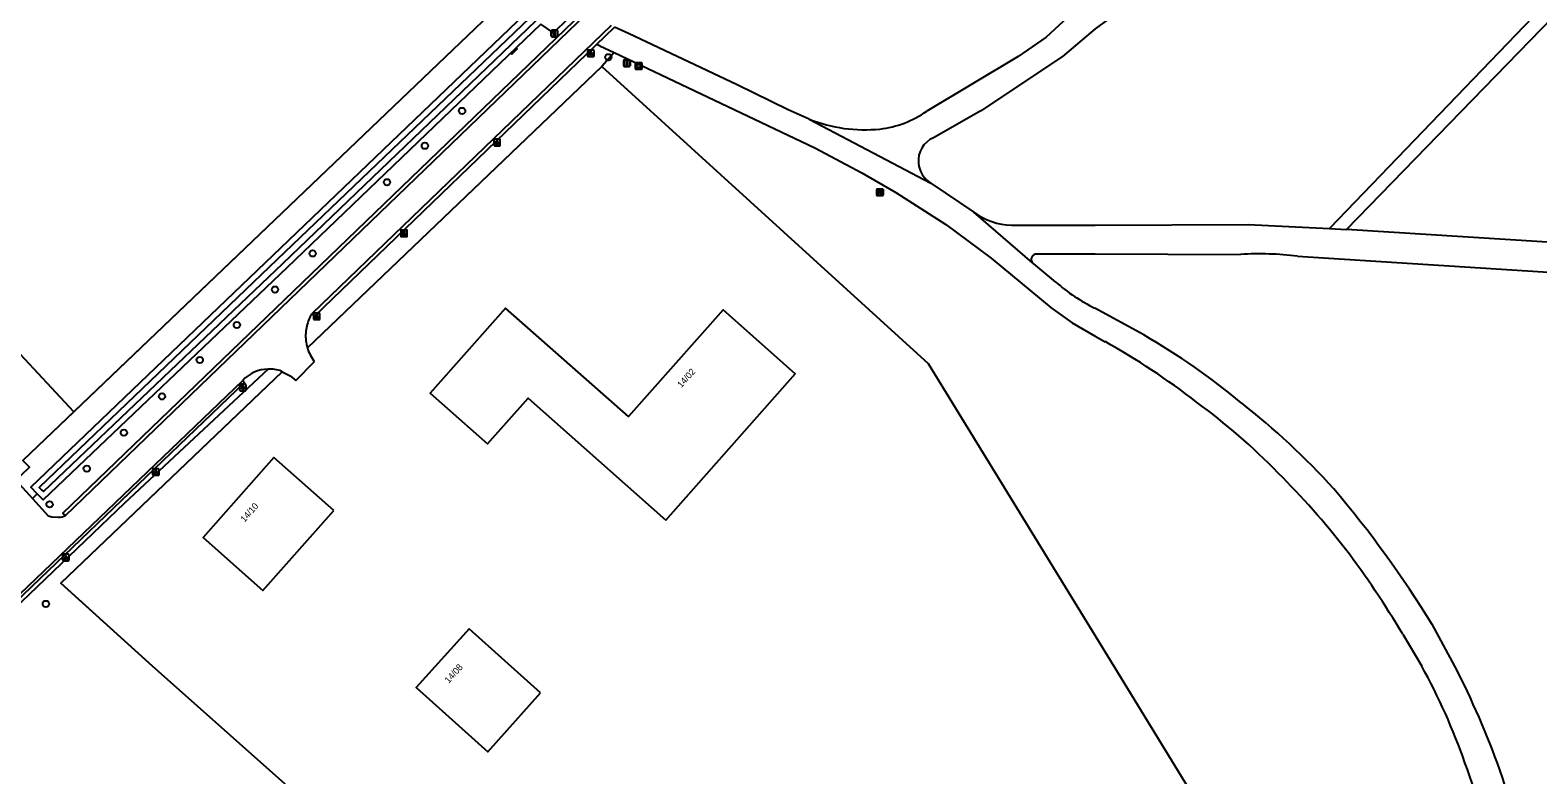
# Model space of a CAD drawing. Extents: x 157154 to 159278, y 385000 to 386650.
# Drawn here: x 157835.7 to 158068.3, y 385983.3 to 386098.1 of the extents above; entities that cross this region are included whole.
import ezdxf

# ---------------------------------------------------------------- set-up
doc = ezdxf.new("R2010")
doc.units = 0
for name, color, linetype in [('IMGEO_Afsluitpaal', 7, 'Continuous'), ('IMGEO_Afvalbak', 7, 'Continuous'), ('IMGEO_Bank', 7, 'Continuous'), ('IMGEO_Boom', 7, 'Continuous'), ('IMGEO_Bouwland', 7, 'Continuous'), ('IMGEO_Gemengd_bos', 7, 'Continuous'), ('IMGEO_Groenvoorziening', 7, 'Continuous'), ('IMGEO_Hek', 7, 'Continuous'), ('IMGEO_Lichtpunt', 7, 'Continuous'), ('IMGEO_Muur', 7, 'Continuous'), ('IMGEO_Pand', 7, 'Continuous'), ('IMGEO_Pand_nummerreeks', 7, 'Continuous'), ('IMGEO_Rijbaan_lokaal_halfverhard', 7, 'Continuous'), ('IMGEO_Rijbaan_lokaal_open', 7, 'Continuous'), ('IMGEO_Verkeersbordpaal', 7, 'Continuous'), ('IMGEO_Voetpad_halfverhard', 7, 'Continuous'), ('IMGEO_Waterloop', 7, 'Continuous')]:
    doc.layers.add(name, color=color, linetype=linetype)

msp = doc.modelspace()

# ---------------------------------------------------------------- linework, layer by layer
at = {"layer": 'IMGEO_Afsluitpaal'}
for p, q in [((157916.1, 386097.15), (157916.1, 386097.95)), ((157916.1, 386097.95), (157916.1, 386097.15)), ((157916.2, 386098.05), (157916.99, 386098.05)), ((157916.99, 386098.05), (157916.2, 386098.05)), ((157916.99, 386097.05), (157916.2, 386097.05)), ((157916.2, 386097.05), (157916.99, 386097.05)), ((157917.09, 386097.95), (157917.09, 386097.15)), ((157917.09, 386097.15), (157917.09, 386097.95))]:
    msp.add_line(p, q, dxfattribs=at)
msp.add_lwpolyline([(157916.52, 386097.93), (157916.67, 386097.93), (157916.67, 386097.18), (157916.52, 386097.18), (157916.52, 386097.93)], dxfattribs=at)
for centre, start, end in [((157916.2, 386097.95), 90, 180), ((157916.2, 386097.95), 90, 180), ((157916.2, 386097.15), 180, 270), ((157916.2, 386097.15), 180, 270), ((157916.99, 386097.95), 0, 90), ((157916.99, 386097.95), 360, 90), ((157916.99, 386097.15), 270, 0), ((157916.99, 386097.15), 270, 0)]:
    msp.add_arc(centre, 0.1, start, end, dxfattribs=at)
at = {"layer": 'IMGEO_Afvalbak'}
for p, q in [((157929.09, 386092.15), (157929.09, 386092.95)), ((157929.09, 386092.95), (157929.09, 386092.15)), ((157929.19, 386093.05), (157929.98, 386093.05)), ((157929.98, 386093.05), (157929.19, 386093.05)), ((157930.08, 386092.95), (157930.08, 386092.15)), ((157930.08, 386092.15), (157930.08, 386092.95)), ((157929.98, 386092.05), (157929.19, 386092.05)), ((157929.19, 386092.05), (157929.98, 386092.05))]:
    msp.add_line(p, q, dxfattribs=at)
msp.add_lwpolyline([(157929.23, 386092.77), (157929.94, 386092.77), (157929.79, 386092.3), (157929.38, 386092.3), (157929.23, 386092.77)], dxfattribs=at)
for centre, start, end in [((157929.19, 386092.95), 90, 180), ((157929.19, 386092.95), 90, 180), ((157929.98, 386092.95), 0, 90), ((157929.98, 386092.95), 360, 90), ((157929.19, 386092.15), 180, 270), ((157929.19, 386092.15), 180, 270), ((157929.98, 386092.15), 270, 0), ((157929.98, 386092.15), 270, 0)]:
    msp.add_arc(centre, 0.1, start, end, dxfattribs=at)
at = {"layer": 'IMGEO_Bank'}
for p, q in [((157966.3, 386072.65), (157966.3, 386073.49)), ((157966.3, 386073.49), (157966.3, 386072.65)), ((157966.37, 386073.57), (157967.22, 386073.57)), ((157967.22, 386073.57), (157966.37, 386073.57)), ((157967.23, 386072.57), (157966.38, 386072.57)), ((157966.38, 386072.57), (157967.23, 386072.57)), ((157967, 386072.97), (157966.6, 386072.97)), ((157966.61, 386073.08), (157966.61, 386073.18)), ((157966.65, 386073.18), (157966.65, 386073.08)), ((157966.94, 386073.19), (157966.66, 386073.19)), ((157966.66, 386073.07), (157966.94, 386073.07)), ((157966.95, 386073.08), (157966.95, 386073.18)), ((157966.99, 386073.18), (157966.99, 386073.08)), ((157967.3, 386073.5), (157967.3, 386072.66)), ((157967.3, 386072.66), (157967.3, 386073.5))]:
    msp.add_line(p, q, dxfattribs=at)
for points in [[(157966.55, 386072.97), (157966.4, 386072.97), (157966.52, 386073.07), (157966.6, 386073.07)], [(157966.6, 386073.19), (157966.52, 386073.19), (157966.52, 386073.35), (157967.08, 386073.35), (157967.08, 386073.19), (157967, 386073.19)], [(157966.6, 386072.96), (157966.6, 386072.75), (157966.55, 386072.75), (157966.55, 386072.96)], [(157967, 386073.07), (157967.08, 386073.07), (157967.19, 386072.97), (157967.05, 386072.97)], [(157967.05, 386072.96), (157967.05, 386072.75), (157967, 386072.75), (157967, 386072.96)]]:
    msp.add_lwpolyline(points, dxfattribs=at)
for centre, radius, start, end in [((157966.38, 386073.49), 0.0779, 92.4484, 184.2845), ((157966.38, 386073.49), 0.0779, 92.4484, 184.2845), ((157966.38, 386072.65), 0.0779, 182.4484, 274.2845), ((157966.38, 386072.65), 0.0779, 182.4484, 274.2845), ((157966.55, 386072.96), 0.00671, 2.8957, 87.1043), ((157966.6, 386073.18), 0.00671, 2.8957, 87.1043), ((157966.6, 386073.08), 0.00671, 272.8957, 357.1043), ((157966.6, 386072.96), 0.00671, 92.8957, 177.1043), ((157966.66, 386073.18), 0.00671, 92.8957, 177.1043), ((157966.66, 386073.08), 0.00671, 182.8957, 267.1043), ((157966.94, 386073.18), 0.00671, 2.8957, 87.1043), ((157966.94, 386073.08), 0.00671, 272.8957, 357.1043), ((157967, 386073.18), 0.00671, 92.8957, 177.1043), ((157967, 386073.08), 0.00671, 182.8957, 267.1043), ((157967, 386072.96), 0.00671, 2.8957, 87.1043), ((157967.05, 386072.96), 0.00671, 92.8957, 177.1043), ((157967.22, 386073.49), 0.0779, 2.4484, 94.2845), ((157967.22, 386073.49), 0.0779, 2.4484, 94.2845), ((157967.22, 386072.65), 0.0779, 272.4484, 4.2845), ((157967.22, 386072.65), 0.0779, 272.4484, 4.2845)]:
    msp.add_arc(centre, radius, start, end, dxfattribs=at)
at = {"layer": 'IMGEO_Boom'}
for centre in [(157924.92, 386093.9), (157902.35, 386085.62), (157896.61, 386080.24), (157890.78, 386074.63), (157879.3, 386063.64), (157873.49, 386058.08), (157867.61, 386052.62), (157861.89, 386047.22), (157856.07, 386041.6), (157850.18, 386036.01), (157844.46, 386030.47), (157838.72, 386024.96), (157838.15, 386009.61)]:
    msp.add_circle(centre, 0.489, dxfattribs=at)
at = {"layer": 'IMGEO_Bouwland'}
for points in [[(157842.48, 386039.2), (157804.71, 386079.73), (157824.5, 386097.81), (157874.85, 386146.92), (157921.22, 386191.28), (157933.34, 386204.01)], [(157907.89, 386100.62), (157906.64, 386100.46), (157842.48, 386039.2)]]:
    msp.add_lwpolyline(points, dxfattribs=at)
at = {"layer": 'IMGEO_Gemengd_bos'}
for points in [[(157925.82, 386094.62), (157923.9, 386092.49)], [(157923.9, 386092.49), (157974.24, 386046.68), (158002.86, 386000), (158038.99, 385941.05), (158062.63, 385902.16)]]:
    msp.add_lwpolyline(points, dxfattribs=at)
at = {"layer": 'IMGEO_Groenvoorziening'}
for points in [[(157836.83, 386026.59), (157835.85, 386027.6), (157873.22, 386063.38), (157912.1, 386100.6)], [(157914.49, 386098.99), (157875.32, 386061.42), (157837.74, 386025.65), (157836.83, 386026.59)], [(157878.48, 386049.1), (157923.9, 386092.49)], [(157872.43, 386045.82), (157850.3, 386025.12), (157807.42, 385984.13), (157804.36, 385981.2)], [(157921.45, 385940.96), (157882.35, 385975.36), (157854.58, 386000), (157840.47, 386012.79), (157874.62, 386045.41)], [(157842.48, 386039.2), (157834.62, 386031.7), (157835.6, 386030.67), (157834.29, 386029.42), (157833.54, 386028.71)], [(157836.83, 386026.59), (157836.07, 386025.87)]]:
    msp.add_lwpolyline(points, dxfattribs=at)
at = {"layer": 'IMGEO_Hek'}
for points in [[(157906.64, 386100.46), (157834.62, 386031.7)], [(157923.9, 386092.49), (157878.48, 386049.1)], [(157874.62, 386045.41), (157840.47, 386012.79)], [(157840.47, 386012.79), (157854.58, 386000), (157882.35, 385975.36), (157921.45, 385940.96)]]:
    msp.add_lwpolyline(points, dxfattribs=at)
at = {"layer": 'IMGEO_Lichtpunt'}
for p, q in [((157921.71, 386094.91), (157921.71, 386094.1)), ((157921.71, 386094.91), (157921.71, 386094.1)), ((157922.61, 386095.01), (157921.81, 386095.01)), ((157922.61, 386095.01), (157921.81, 386095.01)), ((157922.71, 386094.1), (157922.71, 386094.91)), ((157922.71, 386094.1), (157922.71, 386094.91)), ((157921.81, 386094.01), (157922.61, 386094.01)), ((157921.81, 386094.01), (157922.61, 386094.01)), ((157907.25, 386081.14), (157907.25, 386080.33)), ((157907.25, 386081.14), (157907.25, 386080.33)), ((157908.15, 386081.24), (157907.34, 386081.24)), ((157908.15, 386081.24), (157907.34, 386081.24)), ((157908.24, 386080.33), (157908.24, 386081.14)), ((157908.24, 386080.33), (157908.24, 386081.14)), ((157907.34, 386080.24), (157908.15, 386080.24)), ((157907.34, 386080.24), (157908.15, 386080.24)), ((157892.9, 386067.14), (157892.9, 386066.33)), ((157892.9, 386067.14), (157892.9, 386066.33)), ((157893.8, 386067.23), (157892.99, 386067.23)), ((157893.8, 386067.23), (157892.99, 386067.23)), ((157893.9, 386066.33), (157893.9, 386067.14)), ((157893.9, 386066.33), (157893.9, 386067.14)), ((157892.99, 386066.24), (157893.8, 386066.24)), ((157892.99, 386066.24), (157893.8, 386066.24)), ((157879.43, 386054.34), (157879.43, 386053.53)), ((157879.43, 386054.34), (157879.43, 386053.53)), ((157880.34, 386054.43), (157879.53, 386054.43)), ((157880.34, 386054.43), (157879.53, 386054.43)), ((157879.53, 386053.44), (157880.34, 386053.44)), ((157879.53, 386053.44), (157880.34, 386053.44)), ((157880.43, 386053.53), (157880.43, 386054.34)), ((157880.43, 386053.53), (157880.43, 386054.34)), ((157868.94, 386043.48), (157868.13, 386043.48)), ((157868.94, 386043.48), (157868.13, 386043.48)), ((157868.04, 386043.38), (157868.04, 386042.57)), ((157868.04, 386043.38), (157868.04, 386042.57)), ((157868.13, 386042.48), (157868.94, 386042.48)), ((157868.13, 386042.48), (157868.94, 386042.48)), ((157869.04, 386042.57), (157869.04, 386043.38)), ((157869.04, 386042.57), (157869.04, 386043.38)), ((157854.61, 386030.34), (157854.61, 386029.54)), ((157854.61, 386030.34), (157854.61, 386029.54)), ((157855.51, 386030.44), (157854.7, 386030.44)), ((157855.51, 386030.44), (157854.7, 386030.44)), ((157855.6, 386029.54), (157855.6, 386030.34)), ((157855.6, 386029.54), (157855.6, 386030.34)), ((157854.7, 386029.44), (157855.51, 386029.44)), ((157854.7, 386029.44), (157855.51, 386029.44)), ((157840.73, 386017.16), (157840.73, 386016.35)), ((157840.73, 386017.16), (157840.73, 386016.35)), ((157841.63, 386017.26), (157840.82, 386017.26)), ((157841.63, 386017.26), (157840.82, 386017.26)), ((157840.82, 386016.26), (157841.63, 386016.26)), ((157840.82, 386016.26), (157841.63, 386016.26)), ((157841.72, 386016.35), (157841.72, 386017.16)), ((157841.72, 386016.35), (157841.72, 386017.16))]:
    msp.add_line(p, q, dxfattribs=at)
for points in [[(157922.09, 386094.57), (157922.12, 386094.55), (157921.94, 386094.28), (157921.9, 386094.31), (157922.09, 386094.57)], [(157922.19, 386094.53), (157922.23, 386094.53), (157922.23, 386094.2), (157922.19, 386094.2), (157922.19, 386094.53)], [(157922.3, 386094.55), (157922.34, 386094.57), (157922.52, 386094.31), (157922.48, 386094.28), (157922.3, 386094.55)], [(157907.62, 386080.8), (157907.66, 386080.78), (157907.47, 386080.51), (157907.43, 386080.54), (157907.62, 386080.8)], [(157907.72, 386080.76), (157907.77, 386080.76), (157907.77, 386080.43), (157907.72, 386080.43), (157907.72, 386080.76)], [(157907.83, 386080.78), (157907.87, 386080.8), (157908.06, 386080.54), (157908.02, 386080.51), (157907.83, 386080.78)], [(157893.27, 386066.8), (157893.31, 386066.77), (157893.13, 386066.51), (157893.09, 386066.54), (157893.27, 386066.8)], [(157893.38, 386066.75), (157893.42, 386066.75), (157893.42, 386066.43), (157893.38, 386066.43), (157893.38, 386066.75)], [(157893.49, 386066.77), (157893.52, 386066.8), (157893.71, 386066.54), (157893.67, 386066.51), (157893.49, 386066.77)], [(157879.81, 386054), (157879.85, 386053.97), (157879.66, 386053.71), (157879.62, 386053.74), (157879.81, 386054)], [(157879.91, 386053.95), (157879.96, 386053.95), (157879.96, 386053.63), (157879.91, 386053.63), (157879.91, 386053.95)], [(157880.02, 386053.97), (157880.06, 386054), (157880.25, 386053.74), (157880.21, 386053.71), (157880.02, 386053.97)], [(157868.41, 386043.04), (157868.45, 386043.02), (157868.27, 386042.75), (157868.23, 386042.78), (157868.41, 386043.04)], [(157868.52, 386043), (157868.56, 386043), (157868.56, 386042.67), (157868.52, 386042.67), (157868.52, 386043)], [(157868.63, 386043.02), (157868.66, 386043.04), (157868.85, 386042.78), (157868.81, 386042.75), (157868.63, 386043.02)], [(157854.98, 386030.01), (157855.02, 386029.98), (157854.83, 386029.72), (157854.79, 386029.74), (157854.98, 386030.01)], [(157855.08, 386029.96), (157855.13, 386029.96), (157855.13, 386029.64), (157855.08, 386029.64), (157855.08, 386029.96)], [(157855.19, 386029.98), (157855.23, 386030.01), (157855.42, 386029.74), (157855.38, 386029.72), (157855.19, 386029.98)], [(157841.1, 386016.82), (157841.14, 386016.8), (157840.95, 386016.53), (157840.91, 386016.56), (157841.1, 386016.82)], [(157841.2, 386016.78), (157841.25, 386016.78), (157841.25, 386016.45), (157841.2, 386016.45), (157841.2, 386016.78)], [(157841.31, 386016.8), (157841.35, 386016.82), (157841.54, 386016.56), (157841.5, 386016.53), (157841.31, 386016.8)]]:
    msp.add_lwpolyline(points, dxfattribs=at)
for centre in [(157922.21, 386094.71), (157907.75, 386080.94), (157893.4, 386066.94), (157879.93, 386054.14), (157868.54, 386043.18), (157855.11, 386030.14), (157841.23, 386016.96)]:
    msp.add_circle(centre, 0.0994, dxfattribs=at)
for centre, start, end in [((157921.81, 386094.91), 90, 180), ((157921.81, 386094.91), 90, 180), ((157922.61, 386094.91), 0, 90), ((157922.61, 386094.91), 0, 90), ((157921.81, 386094.1), 180, 270), ((157921.81, 386094.1), 180, 270), ((157922.61, 386094.1), 270, 0), ((157922.61, 386094.1), 270, 360), ((157907.34, 386081.14), 90, 180), ((157907.34, 386081.14), 90, 180), ((157908.15, 386081.14), 0, 90), ((157908.15, 386081.14), 0, 90), ((157907.34, 386080.33), 180, 270), ((157907.34, 386080.33), 180, 270), ((157908.15, 386080.33), 270, 0), ((157908.15, 386080.33), 270, 360), ((157892.99, 386067.14), 90, 180), ((157892.99, 386067.14), 90, 180), ((157893.8, 386067.14), 0, 90), ((157893.8, 386067.14), 0, 90), ((157892.99, 386066.33), 180, 270), ((157892.99, 386066.33), 180, 270), ((157893.8, 386066.33), 270, 0), ((157893.8, 386066.33), 270, 360), ((157879.53, 386054.34), 90, 180), ((157879.53, 386054.34), 90, 180), ((157879.53, 386053.53), 180, 270), ((157879.53, 386053.53), 180, 270), ((157880.34, 386054.34), 0, 90), ((157880.34, 386054.34), 0, 90), ((157880.34, 386053.53), 270, 0), ((157880.34, 386053.53), 270, 360), ((157868.13, 386043.38), 90, 180), ((157868.13, 386043.38), 90, 180), ((157868.94, 386043.38), 0, 90), ((157868.94, 386043.38), 0, 90), ((157868.13, 386042.57), 180, 270), ((157868.13, 386042.57), 180, 270), ((157868.94, 386042.57), 270, 0), ((157868.94, 386042.57), 270, 360), ((157854.7, 386030.34), 90, 180), ((157854.7, 386030.34), 90, 180), ((157854.7, 386029.54), 180, 270), ((157854.7, 386029.54), 180, 270), ((157855.51, 386030.34), 0, 90), ((157855.51, 386030.34), 0, 90), ((157855.51, 386029.54), 270, 0), ((157855.51, 386029.54), 270, 360), ((157840.82, 386017.16), 90, 180), ((157840.82, 386017.16), 90, 180), ((157840.82, 386016.35), 180, 270), ((157840.82, 386016.35), 180, 270), ((157841.63, 386017.16), 0, 90), ((157841.63, 386017.16), 0, 90), ((157841.63, 386016.35), 270, 0), ((157841.63, 386016.35), 270, 360)]:
    msp.add_arc(centre, 0.0946, start, end, dxfattribs=at)
at = {"layer": 'IMGEO_Muur'}
msp.add_lwpolyline([(157910.71, 386095.32), (157910.85, 386095.17), (157910.04, 386094.36), (157909.89, 386094.51), (157910.71, 386095.32)], dxfattribs=at)
at = {"layer": 'IMGEO_Pand'}
for points in [[(157933.76, 386022.54), (157953.75, 386045.09), (157942.6, 386054.97), (157928, 386038.49), (157909.05, 386055.2), (157897.44, 386042.09), (157906.25, 386034.28), (157912.52, 386041.35), (157933.76, 386022.54)], [(157882.55, 386024.03), (157873.32, 386032.2), (157862.39, 386019.85), (157871.62, 386011.68), (157882.55, 386024.03)], [(157914.46, 385995.9), (157903.44, 386005.78), (157895.29, 385996.7), (157906.31, 385986.82), (157914.46, 385995.9)]]:
    msp.add_lwpolyline(points, dxfattribs=at)
at = {"layer": 'IMGEO_Rijbaan_lokaal_halfverhard'}
for points in [[(157990.35, 386062.19), (157981.31, 386070.02)], [(157987.09, 386068.01), (158000, 386067.99), (158023.58, 386068.11), (158036.13, 386067.47)], [(158036.13, 386067.47), (158038.78, 386067.31)], [(158117.88, 386062.34), (158038.78, 386067.31)], [(157991, 386063.56), (158000, 386063.59), (158022.42, 386063.49)], [(158031.2, 386063.2), (158199.76, 386052.5), (158200.51, 386052.43)]]:
    msp.add_lwpolyline(points, dxfattribs=at)
for centre, radius, start, end in [((157987.36, 386078.09), 10.09, 233.1642, 268.4917), ((157990.97, 386062.73), 0.826, 88.0326, 221.3038), ((158025.35, 386018.45), 45.13, 82.5506, 93.7168)]:
    msp.add_arc(centre, radius, start, end, dxfattribs=at)
at = {"layer": 'IMGEO_Rijbaan_lokaal_open'}
for points in [[(157841.16, 386023.24), (157840.78, 386023.62), (157877.74, 386059.18), (157921.03, 386100.83)], [(157841.16, 386023.24), (157921.53, 386100.59)], [(157925.37, 386098.78), (157879.21, 386054.36)], [(157923.02, 386095.83), (157925.85, 386098.55)], [(157879.21, 386054.36), (157879.56, 386053.99), (157923.02, 386095.83)], [(157874.62, 386045.41), (157875.82, 386044.76), (157876.7, 386044.05), (157879.56, 386046.98)], [(157790.9, 385971.9), (157804.17, 385982.59), (157807.12, 385985.32), (157868.51, 386044.07)], [(157868.51, 386044.07), (157868.81, 386043.75), (157825.77, 386002.54), (157806.71, 385984.19), (157804.48, 385982.22), (157791.24, 385971.51)], [(157874.46, 386045.51), (157874.62, 386045.41)], [(157833.54, 386028.71), (157836.07, 386025.87)], [(157836.07, 386025.87), (157838.49, 386023.17), (157839.07, 386023.03), (157840.1, 386022.98)]]:
    msp.add_lwpolyline(points, dxfattribs=at)
for centre, radius, start, end in [((157884.67, 386050.93), 6.46, 147.8859, 166.4468), ((157884.66, 386050.92), 6.44, 175.9863, 196.4282), ((157884.55, 386050.95), 6.33, 166.3795, 176.1926), ((157884.67, 386050.92), 6.45, 196.3579, 217.5705), ((157872.6, 386040.17), 5.65, 91.7167, 136.3331), ((157872.6, 386040.19), 5.63, 70.7164, 91.7616), ((157840.26, 386024.56), 1.59, 264.1729, 304.4078)]:
    msp.add_arc(centre, radius, start, end, dxfattribs=at)
at = {"layer": 'IMGEO_Verkeersbordpaal'}
for p, q in [((157927.28, 386092.58), (157927.28, 386093.37)), ((157927.28, 386093.37), (157927.28, 386092.58)), ((157927.38, 386093.47), (157928.17, 386093.47)), ((157928.17, 386093.47), (157927.38, 386093.47)), ((157928.17, 386092.48), (157927.38, 386092.48)), ((157927.38, 386092.48), (157928.17, 386092.48)), ((157928.27, 386093.37), (157928.27, 386092.58)), ((157928.27, 386092.58), (157928.27, 386093.37))]:
    msp.add_line(p, q, dxfattribs=at)
msp.add_lwpolyline([(157927.7, 386093.35), (157927.85, 386093.35), (157927.85, 386092.6), (157927.7, 386092.6), (157927.7, 386093.35)], dxfattribs=at)
for centre, start, end in [((157927.38, 386093.37), 90, 180), ((157927.38, 386093.37), 90, 180), ((157927.38, 386092.58), 180, 270), ((157927.38, 386092.58), 180, 270), ((157928.17, 386093.37), 0, 90), ((157928.17, 386093.37), 360, 90), ((157928.17, 386092.58), 270, 0), ((157928.17, 386092.58), 270, 0)]:
    msp.add_arc(centre, 0.1, start, end, dxfattribs=at)
at = {"layer": 'IMGEO_Voetpad_halfverhard'}
for points in [[(158195.55, 386286.9), (158186.3, 386273.09), (158173.2, 386254.3), (158169.79, 386250), (158158.13, 386235.29), (158145.23, 386220.42), (158120.62, 386194.82), (158112.14, 386186.95), (158107.92, 386183.38), (158086.4, 386166.54), (158077.82, 386159.59), (158000, 386103.11), (157995.75, 386100.02), (157992.43, 386096.99), (157988.12, 386093.99), (157974.03, 386085.58)], [(158152.88, 386222.71), (158147.7, 386217.13), (158122.06, 386190.41), (158118.02, 386186.75), (158107.54, 386178.07), (158081.09, 386157.29), (158073.66, 386151.71), (158061.29, 386142.97), (158000, 386098.3), (157994.97, 386093.99), (157982.35, 386085.62), (157975.05, 386081.48)], [(157916.5, 386100.92), (157918.67, 386099.84), (157916.45, 386097.68), (157914.49, 386098.99)], [(157955.9, 386084.35), (157952.64, 386085.78), (157944.77, 386089.65), (157928, 386097.54), (157925.85, 386098.55)], [(157923.61, 386095.67), (157925.82, 386094.62)], [(157925.82, 386094.62), (157956.78, 386079.93), (157964.03, 386076.09), (157969.25, 386073.06), (157976.98, 386068.09), (157983.96, 386062.91), (157993.21, 386055.25), (157996.46, 386052.93), (158000, 386050.87), (158001.54, 386050.04)], [(157955.9, 386084.35), (157974.67, 386074.48)], [(157974.67, 386074.48), (157981.31, 386070.02)], [(157993.95, 386059.23), (157990.52, 386062.04)], [(158007.51, 386051.07), (157999.93, 386055.22)], [(158055.5, 386000), (158051.98, 386006.46)], [(158047.44, 386004.93), (158050.38, 386000)]]:
    msp.add_lwpolyline(points, dxfattribs=at)
for centre, radius, start, end in [((157922.28, 386091.94), 3.96, 70.3485, 79.2232), ((157964.96, 386098.53), 15.81, 276.6604, 304.9787), ((157964.46, 386105.85), 23.14, 248.2981, 275.7996), ((157976.58, 386077.94), 3.86, 113.3376, 185.6241), ((157976.86, 386078), 4.15, 186.1016, 237.9661), ((157990.97, 386062.73), 0.828, 221.414, 237.1643), ((158012.66, 386080.7), 28.49, 228.9238, 243.4489), ((157953.79, 385957.9), 107.55, 50.2613, 60.0319), ((157947.3, 385952.64), 111.49, 52.1988, 60.8877), ((157956.96, 385960.41), 99.47, 44.2202, 53.8533), ((157950.76, 385949.16), 116.26, 42.2566, 51.867), ((157938.23, 385939.58), 127.43, 38.0162, 45.0575), ((157904.96, 385915.58), 172.84, 31.7213, 40.2852), ((157922.7, 385930.71), 145.15, 30.7523, 37.0015), ((157967.49, 385954.01), 94.79, 19.1586, 29.0254), ((157933.6, 385937.69), 136.9, 19.7925, 27.0745), ((157934.8, 385939.53), 130.45, 12.5947, 20.4545), ((157939.5, 385942.65), 129.7, 8.6355, 18.6126)]:
    msp.add_arc(centre, radius, start, end, dxfattribs=at)
at = {"layer": 'IMGEO_Waterloop'}
for points in [[(158241.2, 386414.41), (157914.69, 386101.81), (157914.45, 386101.59), (157912.88, 386100.08), (157912.73, 386099.94), (157873.85, 386062.72), (157837.14, 386027.57), (157837.48, 386027.22), (157837.76, 386026.94), (157874.69, 386062.08), (157913.72, 386099.52), (157913.86, 386099.65), (157915.63, 386101.35), (157915.86, 386101.58), (157920.89, 386106.4), (157941.32, 386125.21), (157976.47, 386158.82), (157999.36, 386181.41), (158142.89, 386318.48), (158243.42, 386414.21)], [(158173.11, 386171.31), (158172.88, 386171.27), (158128.87, 386163.86), (158036.13, 386067.47)], [(158038.78, 386067.31), (158130.8, 386162.05), (158171.36, 386168.61)]]:
    msp.add_lwpolyline(points, dxfattribs=at)

# ---------------------------------------------------------------- texts
at = {"layer": 'IMGEO_Pand_nummerreeks'}
for s, rotation, p in [('14/02', 48.1817, (157936.18, 386042.86)), ('14/10', 48.5298, (157868.8, 386022.13)), ('14/08', 48.0086, (157900.3, 385997.3))]:
    msp.add_text(s, height=1, rotation=rotation, dxfattribs=at).set_placement(p)

doc.saveas('drawing.dxf')
